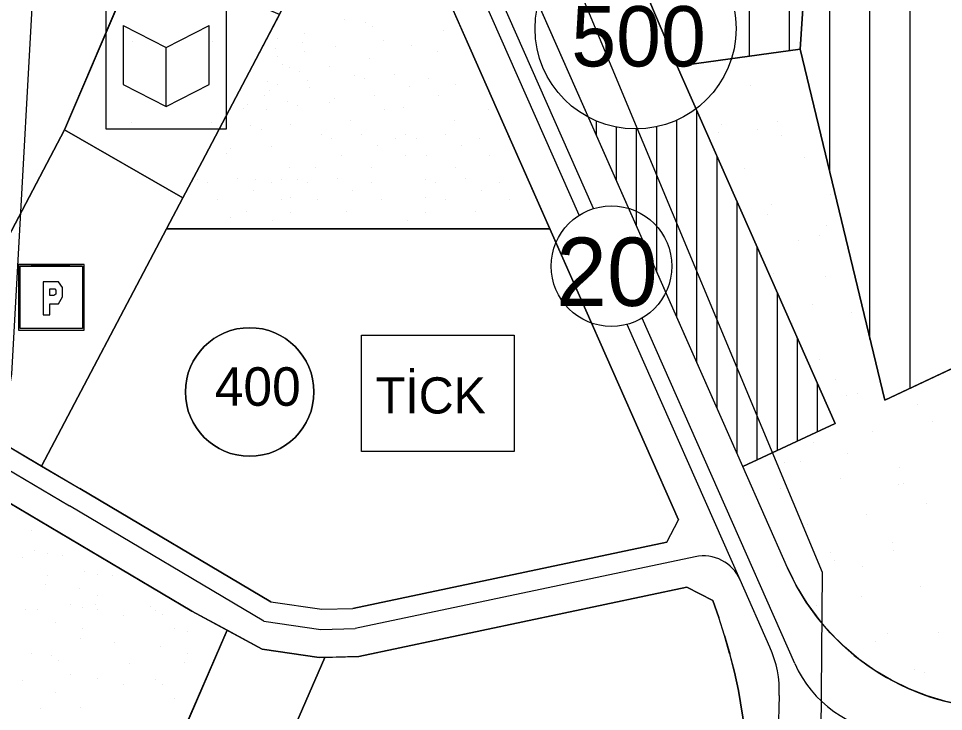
# Model space of a CAD drawing. Extents: x 419109 to 421295, y 4452223 to 4457798.
# Drawn here: x 420389.8 to 420619.9, y 4452312 to 4452484.4 of the extents above; entities that cross this region are included whole.
import ezdxf

# ---------------------------------------------------------------- set-up
doc = ezdxf.new("R2010")
doc.units = 0
for name, color, linetype in [('ADA', 7, 'Continuous'), ('ADAKENARI', 7, 'Continuous'), ('Default', 7, 'Continuous'), ('KALDIRIM', 7, 'Continuous'), ('KD_DAIRE', 7, 'Continuous'), ('KD_YGEN', 7, 'Continuous'), ('LJ_SEMBOL', 7, 'Continuous'), ('PL_AYA_PARK_DINLENME', 7, 'Continuous'), ('PL_GENEL_OTOPARK', 7, 'Continuous'), ('PL_KON_MEV_350', 7, 'Continuous'), ('PL_KON_MEV_500', 7, 'Continuous'), ('PL_SAY_KULTUR_TESIS', 7, 'Continuous'), ('PL_TİCK', 7, 'Continuous'), ('SM_DAIRE', 7, 'Continuous'), ('SM_TAKS', 7, 'Continuous'), ('SN_3_DERECE_KAYNAK_KORUMA', 7, 'Continuous'), ('SN_KENTSEL_DONUSUM', 7, 'Continuous'), ('TR_KULTURELTESIS', 7, 'Continuous'), ('TR_ORTAYOGUNKONUT', 7, 'Continuous'), ('TR_PARKALANI', 7, 'Continuous'), ('TR_TİCK', 7, 'Continuous'), ('TR_YUKSEKYOGUNKONUT', 7, 'Continuous')]:
    doc.layers.add(name, color=color, linetype=linetype)

# ---------------------------------------------------------------- blocks, each defined once
blk = doc.blocks.new('POINT_DISPLAY')
at = {"layer": 'Default'}
blk.add_line((0, 0), (0, 0), dxfattribs=at)

msp = doc.modelspace()

# ---------------------------------------------------------------- linework, layer by layer
at = {"layer": 'ADA'}
for p, q in [((420553.65, 4452472.53), (420511.62, 4452571.53)), ((420438.38, 4452543.76), (420401.24, 4452456.66)), ((420456, 4452487.81), (420435.44, 4452448.79)), ((420502.09, 4452477.06), (420508.96, 4452461.5)), ((420584.26, 4452476.75), (420553.65, 4452472.53)), ((420605.28, 4452389.43), (420584.26, 4452476.75)), ((420553.65, 4452472.53), (420592.92, 4452383.64)), ((420401.24, 4452456.66), (420366.25, 4452390.22)), ((420430.68, 4452439.74), (420401.24, 4452456.66)), ((420435.44, 4452448.79), (420430.68, 4452439.74)), ((420395.54, 4452373.03), (420430.68, 4452439.74)), ((420426.62, 4452432.05), (420521.98, 4452432.05)), ((420632.81, 4452402.34), (420605.28, 4452389.43)), ((420592.92, 4452383.64), (420569.99, 4452372.88)), ((420551.09, 4452354.08), (420553.96, 4452359.68)), ((420556.04, 4452342.86), (420562.52, 4452339.54)), ((420565.42, 4452330.88), (420563.99, 4452335.37)), ((420441.71, 4452332.18), (420418.97, 4452279.89))]:
    msp.add_line(p, q, dxfattribs=at)
at = {"layer": 'ADAKENARI'}
for p, q in [((420569.99, 4452372.88), (420498.57, 4452534.49)), ((420493.27, 4452497.02), (420502.09, 4452477.06)), ((420508.96, 4452461.5), (420529.34, 4452415.38)), ((420529.34, 4452415.38), (420553.96, 4452359.68)), ((420317.78, 4452405.13), (420432.92, 4452336.96)), ((420369.7, 4452388.33), (420405.01, 4452367.43)), ((420581.12, 4452347.7), (420569.99, 4452372.88)), ((420452.56, 4452339.28), (420405.01, 4452367.43)), ((420551.09, 4452354.08), (420472.99, 4452337.63)), ((420474.42, 4452325.67), (420556.04, 4452342.86)), ((420452.56, 4452339.28), (420465.28, 4452337.4)), ((420562.52, 4452339.54), (420563.99, 4452335.37)), ((420432.92, 4452336.96), (420450.38, 4452327.47)), ((420465.28, 4452337.4), (420472.99, 4452337.63)), ((420565.42, 4452330.88), (420566.72, 4452326.35)), ((420450.38, 4452327.47), (420464.58, 4452325.37)), ((420443.23, 4452273), (420466.03, 4452325.42)), ((420464.58, 4452325.37), (420474.42, 4452325.67)), ((420566.7, 4452326.39), (420567.87, 4452321.78)), ((420567.87, 4452321.78), (420568.88, 4452317.19)), ((420568.88, 4452317.19), (420570.52, 4452307.53))]:
    msp.add_line(p, q, dxfattribs=at)
msp.add_arc((420634.85, 4452371.44), 58.74, 203.8418, 265.3344, dxfattribs=at)
at = {"layer": 'KALDIRIM'}
for p, q in [((420532.87, 4452437.08), (420491.59, 4452530.5)), ((420529.24, 4452435.4), (420492.46, 4452518.63)), ((420569.32, 4452344.71), (420541.23, 4452408.28)), ((420582.89, 4452323.91), (420544.92, 4452409.83)), ((420367.15, 4452384.03), (420402.47, 4452363.12)), ((420450.86, 4452334.47), (420402.47, 4452363.12)), ((420558.12, 4452350.45), (420473.58, 4452332.65)), ((420576.73, 4452327.95), (420569.32, 4452344.71)), ((420450.86, 4452334.47), (420464.99, 4452332.39)), ((420464.99, 4452332.39), (420473.58, 4452332.65)), ((420579.05, 4452315.94), (420576.14, 4452230.28))]:
    msp.add_line(p, q, dxfattribs=at)
for centre, radius, start, end in [((420560.18, 4452340.67), 10, 23.8418, 101.8918), ((420551.65, 4452316.87), 27.42, 358.0559, 23.8418), ((420609.38, 4452335.62), 28.97, 203.8418, 265.3344)]:
    msp.add_arc(centre, radius, start, end, dxfattribs=at)
at = {"layer": 'KD_DAIRE'}
msp.add_circle((420537.31, 4452422.75), 15, dxfattribs=at)
at = {"layer": 'LJ_SEMBOL'}
for p, q in [((420415.86, 4452482.6), (420426.55, 4452477.15)), ((420415.86, 4452482.6), (420415.86, 4452467.94)), ((420426.55, 4452477.15), (420437.24, 4452482.6)), ((420437.24, 4452467.94), (420437.24, 4452482.6)), ((420426.55, 4452462.49), (420426.55, 4452477.15)), ((420415.86, 4452467.94), (420426.55, 4452462.49)), ((420426.55, 4452462.49), (420437.24, 4452467.94))]:
    msp.add_line(p, q, dxfattribs=at)
for points in [[(420411.55, 4452456.89), (420441.55, 4452456.89), (420441.55, 4452486.89), (420411.55, 4452486.89)], [(420475.15, 4452405.61), (420513.08, 4452405.61), (420513.08, 4452376.67), (420475.15, 4452376.67)]]:
    msp.add_lwpolyline(points, close=True, dxfattribs=at)
for points in [[(420406.1, 4452423.15), (420389.81, 4452423.15), (420405.69, 4452422.75), (420405.69, 4452407.27), (420390.22, 4452407.27), (420390.22, 4452422.75), (420405.69, 4452422.75), (420389.81, 4452423.15), (420389.81, 4452406.87), (420406.1, 4452406.87), (420406.1, 4452423.15)], [(420400.71, 4452417.46), (420399.76, 4452418.82), (420399.05, 4452418.82), (420395.96, 4452418.82), (420395.96, 4452410.68), (420397.62, 4452410.68), (420397.62, 4452413.39), (420398.81, 4452413.39), (420399.76, 4452413.39), (420400.71, 4452415.09), (420400.71, 4452416.45), (420400.71, 4452417.46)], [(420397.62, 4452415.43), (420397.62, 4452417.12), (420398.1, 4452417.12), (420398.81, 4452417.12), (420399.05, 4452416.79), (420399.05, 4452416.11), (420399.05, 4452415.77), (420398.57, 4452415.43), (420398.1, 4452415.43), (420397.62, 4452415.43)]]:
    msp.add_lwpolyline(points, dxfattribs=at)
at = {"layer": 'PL_AYA_PARK_DINLENME'}
for points in [[(420477.38, 4452523.34), (420456, 4452487.81), (420454.71, 4452485.36), (420435.44, 4452448.79), (420430.68, 4452439.74), (420426.62, 4452432.05), (420521.98, 4452432.05), (420521.98, 4452432.05), (420508.96, 4452461.5), (420502.09, 4452477.06), (420493.27, 4452497.02), (420492.14, 4452499.45), (420490.93, 4452501.84), (420489.63, 4452504.19), (420480.57, 4452519.3)], [(420570.14, 4452230.34), (420570.36, 4452236.91), (420443.23, 4452273), (420418.97, 4452279.89), (420441.71, 4452332.18), (420432.92, 4452336.96), (420317.78, 4452405.13), (420276.27, 4452430.86), (420253.59, 4452444.29), (420237.9, 4452453.57)]]:
    msp.add_lwpolyline(points, dxfattribs=at)
msp.add_lwpolyline([(420630.07, 4452312.9), (420625.26, 4452313.49), (420620.51, 4452314.48), (420615.86, 4452315.85), (420611.34, 4452317.61), (420606.99, 4452319.73), (420602.82, 4452322.2), (420598.86, 4452325.01), (420595.16, 4452328.14), (420591.72, 4452331.56), (420588.58, 4452335.25), (420585.75, 4452339.19), (420583.26, 4452343.35), (420581.12, 4452347.7), (420569.99, 4452372.88), (420592.92, 4452383.64), (420553.65, 4452472.53), (420584.26, 4452476.75), (420605.28, 4452389.43), (420632.81, 4452402.34), (420639.96, 4452312.09)], close=True, dxfattribs=at)
at = {"layer": 'PL_GENEL_OTOPARK'}
for points in [[(420366.31, 4452390.34), (420369.7, 4452388.33), (420395.54, 4452373.03), (420426.62, 4452432.05), (420430.68, 4452439.74), (420401.24, 4452456.66), (420366.31, 4452390.34)], [(420466.03, 4452325.42), (420464.58, 4452325.37), (420450.38, 4452327.47), (420441.71, 4452332.18), (420418.97, 4452279.89), (420443.23, 4452273), (420466.03, 4452325.42)]]:
    msp.add_lwpolyline(points, dxfattribs=at)
at = {"layer": 'PL_KON_MEV_350'}
for points in [[(420585.88, 4452501.96), (420584.26, 4452476.75), (420553.65, 4452472.53), (420511.62, 4452571.53)], [(420632.81, 4452402.34), (420605.28, 4452389.43), (420584.26, 4452476.75), (420585.88, 4452501.96)]]:
    msp.add_lwpolyline(points, dxfattribs=at)
at = {"layer": 'PL_KON_MEV_500'}
msp.add_lwpolyline([(420569.99, 4452372.88), (420498.57, 4452534.49), (420499.75, 4452552.17), (420511.62, 4452571.53), (420553.65, 4452472.53), (420592.92, 4452383.64)], close=True, dxfattribs=at)
at = {"layer": 'PL_SAY_KULTUR_TESIS'}
msp.add_lwpolyline([(420454.71, 4452485.36), (420419.76, 4452500.1), (420401.24, 4452456.66), (420430.68, 4452439.74), (420435.44, 4452448.79), (420454.71, 4452485.36)], dxfattribs=at)
at = {"layer": 'PL_TİCK'}
for points in [[(420276.25, 4452443.66), (420281.87, 4452440.33), (420366.31, 4452390.34), (420401.24, 4452456.66), (420419.76, 4452500.1), (420438.38, 4452543.76), (420430.76, 4452547.54), (420412.06, 4452556.81), (420367.8, 4452578.76), (420361.98, 4452581.65), (420333.09, 4452507.03), (420320.59, 4452492), (420276.25, 4452443.66)], [(420395.54, 4452373.03), (420405.01, 4452367.43), (420452.56, 4452339.28), (420465.28, 4452337.4), (420472.99, 4452337.63), (420551.09, 4452354.08), (420553.96, 4452359.68), (420529.34, 4452415.38), (420521.98, 4452432.05), (420521.98, 4452432.05), (420426.62, 4452432.05), (420395.54, 4452373.03)], [(420443.23, 4452273), (420570.36, 4452236.91), (420570.68, 4452246.18), (420571.88, 4452281.56), (420571.95, 4452284.66), (420571.96, 4452287.94), (420571.86, 4452292.83), (420571.55, 4452297.75), (420571.28, 4452301.02), (420570.94, 4452304.28), (420570.52, 4452307.53), (420568.88, 4452317.19), (420567.87, 4452321.78), (420566.71, 4452326.35), (420566.7, 4452326.39), (420565.42, 4452330.88), (420563.99, 4452335.37), (420562.52, 4452339.54), (420556.04, 4452342.86), (420474.42, 4452325.67), (420466.03, 4452325.42), (420443.23, 4452273)]]:
    msp.add_lwpolyline(points, dxfattribs=at)
at = {"layer": 'SM_DAIRE'}
msp.add_circle((420543.3, 4452481.88), 25, dxfattribs=at)
at = {"layer": 'SM_TAKS'}
msp.add_circle((420447.29, 4452391.46), 15.99, dxfattribs=at)
at = {"layer": 'SN_3_DERECE_KAYNAK_KORUMA'}
msp.add_lwpolyline([(420357.81, 4452232.59), (420364.57, 4452258.77), (420388.14, 4452395.87), (420395.04, 4452520.02), (420383.4, 4452655.62), (420344.11, 4452773.22), (420290.77, 4452875.07), (420213.22, 4452980.45), (420010.57, 4453225.26), (419772.92, 4453473.96), (419554.68, 4453657.1), (419332.55, 4453805.23), (419159.82, 4453894.89), (419126.5, 4453906.07)], dxfattribs=at)
at = {"layer": 'SN_KENTSEL_DONUSUM'}
for p, q in [((420506.7, 4452545.79), (420589.68, 4452346.63)), ((420589.68, 4452346.63), (420588.78, 4452230.15))]:
    msp.add_line(p, q, dxfattribs=at)
at = {"layer": 'TR_ORTAYOGUNKONUT'}
for p, q in [((420611.62, 4452392.41), (420611.62, 4452600.5)), ((420601.62, 4452404.62), (420601.62, 4452514.91)), ((420571.62, 4452475), (420571.62, 4452510.59)), ((420581.62, 4452476.38), (420581.62, 4452507.52)), ((420591.62, 4452446.16), (420591.62, 4452508.69))]:
    msp.add_line(p, q, dxfattribs=at)
at = {"layer": 'TR_TİCK'}
for points in [[(420361.98, 4452581.65), (420333.09, 4452507.03), (420320.59, 4452492), (420276.25, 4452443.66), (420281.87, 4452440.33), (420366.31, 4452390.34), (420401.24, 4452456.66), (420419.76, 4452500.1), (420438.38, 4452543.76), (420430.76, 4452547.54), (420412.06, 4452556.81), (420367.8, 4452578.76), (420361.98, 4452581.65)], [(420426.62, 4452432.05), (420395.54, 4452373.03), (420405.01, 4452367.43), (420452.56, 4452339.28), (420465.28, 4452337.4), (420472.99, 4452337.63), (420551.09, 4452354.08), (420553.96, 4452359.68), (420529.34, 4452415.38), (420521.98, 4452432.05), (420426.62, 4452432.05)], [(420475.15, 4452376.67), (420475.15, 4452405.61), (420513.08, 4452405.61), (420513.08, 4452376.67), (420475.15, 4452376.67)], [(420443.23, 4452273), (420570.36, 4452236.91), (420570.68, 4452246.18), (420571.88, 4452281.56), (420571.95, 4452284.66), (420571.96, 4452287.94), (420571.86, 4452292.83), (420571.55, 4452297.75), (420571.28, 4452301.02), (420570.94, 4452304.28), (420570.52, 4452307.53), (420568.88, 4452317.19), (420567.87, 4452321.78), (420566.71, 4452326.35), (420566.7, 4452326.39), (420565.42, 4452330.88), (420563.99, 4452335.37), (420562.52, 4452339.54), (420556.04, 4452342.86), (420474.42, 4452325.67), (420466.03, 4452325.42), (420443.23, 4452273)]]:
    msp.add_lwpolyline(points, dxfattribs=at)
for start, end in [(0, 180), (180, 0)]:
    msp.add_arc((420447.29, 4452391.46), 15.99, start, end, dxfattribs=at)
at = {"layer": 'TR_YUKSEKYOGUNKONUT'}
for p, q in [((420558.57, 4452398.72), (420558.57, 4452461.39)), ((420533.57, 4452455.29), (420533.57, 4452458.85)), ((420553.57, 4452410.04), (420553.57, 4452459.09)), ((420538.57, 4452443.98), (420538.57, 4452457.33)), ((420543.57, 4452432.67), (420543.57, 4452456.88)), ((420548.57, 4452421.35), (420548.57, 4452457.45)), ((420563.57, 4452387.41), (420563.57, 4452450.08)), ((420568.57, 4452376.1), (420568.57, 4452438.76)), ((420573.57, 4452374.56), (420573.57, 4452427.44)), ((420578.57, 4452376.91), (420578.57, 4452416.12)), ((420583.57, 4452379.25), (420583.57, 4452404.8)), ((420588.57, 4452381.6), (420588.57, 4452393.48))]:
    msp.add_line(p, q, dxfattribs=at)

# ---------------------------------------------------------------- block references
at = {"layer": 'TR_KULTURELTESIS', "xscale": 0.1, "yscale": 0.10000000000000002}
for p in [(420418.12, 4452478.58), (420438.12, 4452478.58), (420417.9, 4452458.41), (420437.9, 4452458.41)]:
    msp.add_blockref('POINT_DISPLAY', p, dxfattribs=at)
at = {"layer": 'TR_PARKALANI', "xscale": 0.1, "yscale": 0.10000000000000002}
for p in [(420470.97, 4452484.07), (420476.04, 4452483.44), (420477.78, 4452482.32), (420495.43, 4452481.46), (420454.19, 4452479.29), (420460.87, 4452480.7), (420453.67, 4452476.96), (420460.34, 4452478.37), (420468.77, 4452477.32), (420480.66, 4452478.86), (420487.56, 4452477.73), (420454.3, 4452474.81), (420460.97, 4452476.22), (420493.91, 4452476.18), (420455.52, 4452472.84), (420467.11, 4452472.35), (420477.14, 4452474.34), (420457.1, 4452472.17), (420459.74, 4452471.3), (420473.27, 4452470.29), (420483.28, 4452470.47), (420451.65, 4452468.78), (420454.29, 4452467.92), (420461.66, 4452468.96), (420475.91, 4452469.42), (420491.71, 4452469.42), (420498.44, 4452467.92), (420452.17, 4452466.4), (420462.22, 4452467.08), (420487.15, 4452467.55), (420571.92, 4452467.62), (420451.09, 4452465.28), (420456.77, 4452463.7), (420467.26, 4452463.4), (420468.34, 4452464.52), (420478.39, 4452465.2), (420494.19, 4452465.2), (420557.15, 4452465.02), (420445.64, 4452461.9), (420446.71, 4452463.01), (420451.38, 4452461.74), (420459.31, 4452462.64), (420480.89, 4452461.83), (420485.64, 4452462.26), (420506.78, 4452461.83), (420472.34, 4452458.89), (420498.23, 4452458.89), (420578.58, 4452458.64), (420447.51, 4452457.69), (420450.15, 4452456.82), (420457.52, 4452457.87), (420564.72, 4452457.87), (420573.72, 4452456.67), (420465.11, 4452455.4), (420467.76, 4452454.53), (420475.13, 4452455.57), (420483.55, 4452454.53), (420486.06, 4452455.4), (420488.7, 4452454.53), (420496.07, 4452455.57), (420504.5, 4452454.53), (420563.81, 4452456.04), (420579.49, 4452455.27), (420442.58, 4452451.92), (420452.63, 4452452.61), (420479, 4452452.65), (420499.94, 4452452.65), (420441.5, 4452450.81), (420470.24, 4452450.31), (420486.03, 4452450.31), (420491.18, 4452450.31), (420506.98, 4452450.31), (420585.24, 4452449.66), (420457.31, 4452447.3), (420463.69, 4452447.3), (420477.48, 4452447.37), (420498.43, 4452447.37), (420570.47, 4452447.06), (420434.26, 4452444.4), (420436.9, 4452443.53), (420444.27, 4452444.58), (420448.76, 4452444.35), (420452.7, 4452443.53), (420455.14, 4452444.35), (420459.09, 4452444.4), (420461.73, 4452443.53), (420469.1, 4452444.58), (420477.52, 4452443.53), (420491, 4452444.4), (420493.64, 4452443.53), (420501.01, 4452444.58), (420509.44, 4452443.53), (420448.15, 4452441.66), (420472.97, 4452441.66), (420504.89, 4452441.66), (420591.91, 4452440.69), (420439.39, 4452439.32), (420455.18, 4452439.32), (420457.44, 4452439.92), (420464.21, 4452439.32), (420480, 4452439.32), (420490.96, 4452439.92), (420496.12, 4452439.32), (420511.92, 4452439.32), (420577.13, 4452438.08), (420446.63, 4452436.37), (420457.49, 4452436.09), (420471.45, 4452436.37), (420491, 4452436.09), (420503.37, 4452436.37), (420576.02, 4452435.57), (420442.59, 4452434.88), (420452.93, 4452434.21), (420486.45, 4452434.21), (420434.04, 4452431.94), (420590.79, 4452432.97), (420583.79, 4452429.1), (420589.17, 4452430.47), (420577.68, 4452420.83), (420590.45, 4452420.12), (420587.32, 4452413.27), (420597.11, 4452411.14), (420582.34, 4452408.54), (420589, 4452399.56), (420593.13, 4452394.64), (420595.66, 4452390.58), (420598.62, 4452390.97), (420613.39, 4452388.36), (420617.1, 4452384.2), (420602.32, 4452381.6), (420587.55, 4452378.99), (420596.01, 4452376.2), (420580.37, 4452373.88), (420584.24, 4452374.12), (420608.98, 4452372.62), (420594.21, 4452370.01), (420579.44, 4452367.41), (420608.59, 4452368.44), (420609.92, 4452368.67), (420615.65, 4452363.64), (420600.87, 4452361.03), (420586.1, 4452358.43), (420392.94, 4452356.96), (420607.31, 4452353.9), (420393.78, 4452351.94), (420396.94, 4452351.15), (420400.69, 4452350.81), (420591.67, 4452351.58), (420607.53, 4452352.05), (420390.73, 4452350.21), (420592.76, 4452349.45), (420396.94, 4452345.88), (420406.19, 4452346.86), (420409.35, 4452346.07), (420413.1, 4452345.73), (420599.69, 4452347.93), (420396.41, 4452343.55), (420404.84, 4452342.5), (420614.19, 4452343.07), (420409.35, 4452340.81), (420599.42, 4452340.47), (420391.49, 4452337.42), (420394.49, 4452337.42), (420402.62, 4452338.58), (420405.78, 4452337.8), (420408.82, 4452338.47), (420409.53, 4452337.46), (420422.64, 4452338.16), (420423.95, 4452337.15), (420588.2, 4452338.28), (420415.88, 4452335.9), (420425.7, 4452336.03), (420399.11, 4452334.07), (420405.78, 4452332.53), (420428.57, 4452332.57), (420405.25, 4452330.2), (420431.72, 4452331.78), (420606.08, 4452331.49), (420618.61, 4452331.59), (420413.67, 4452329.15), (420425.06, 4452328.05), (420602.97, 4452329.28), (420392.94, 4452326.5), (420398, 4452325.87), (420431.72, 4452326.52), (420399.75, 4452324.75), (420417.39, 4452323.89), (420431.2, 4452324.18), (420402.62, 4452321.29), (420612.74, 4452322.51), (420615.15, 4452321.73), (420390.73, 4452319.75), (420409.53, 4452320.16), (420415.88, 4452318.6), (420423.95, 4452319.85), (420425.7, 4452318.73), (420399.11, 4452316.77), (420428.57, 4452315.27), (420395.24, 4452312.72), (420405.25, 4452312.9)]:
    msp.add_blockref('POINT_DISPLAY', p, dxfattribs=at)

# ---------------------------------------------------------------- texts
at = {"layer": 'KD_YGEN'}
msp.add_text('20', height=17, dxfattribs=at).set_placement((420523.54, 4452412.86))
at = {"layer": 'LJ_SEMBOL'}
msp.add_text('TİCK', height=9, dxfattribs=at).set_placement((420478.66, 4452386.1))
at = {"layer": 'SM_TAKS'}
for s, height, p in [('500', 15, (420527.31, 4452472.44)), ('400', 9.593, (420438.61, 4452388.01))]:
    msp.add_text(s, height=height, dxfattribs=at).set_placement(p)

doc.saveas('drawing.dxf')
